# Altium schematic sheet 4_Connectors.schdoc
size 309 x 223 mm; Symbol: Artery_A4; Device: Artery_A4; @Project Name: AT-START-M412; @Page Count: 4; @Create Date: 2024-06-20; Company: Artery Technology; Drawed: SD; Version: 1.0; Page Size: A4; @Update Date: 2024-09-05; @Page No: 4; @Schematic Name: AT-START-M412-V1.0; @Page Name: Connectors; @Board Name: AT-START-M412-V1.0; @Create Time: 16:55:15; @Update Time: 09:29:06
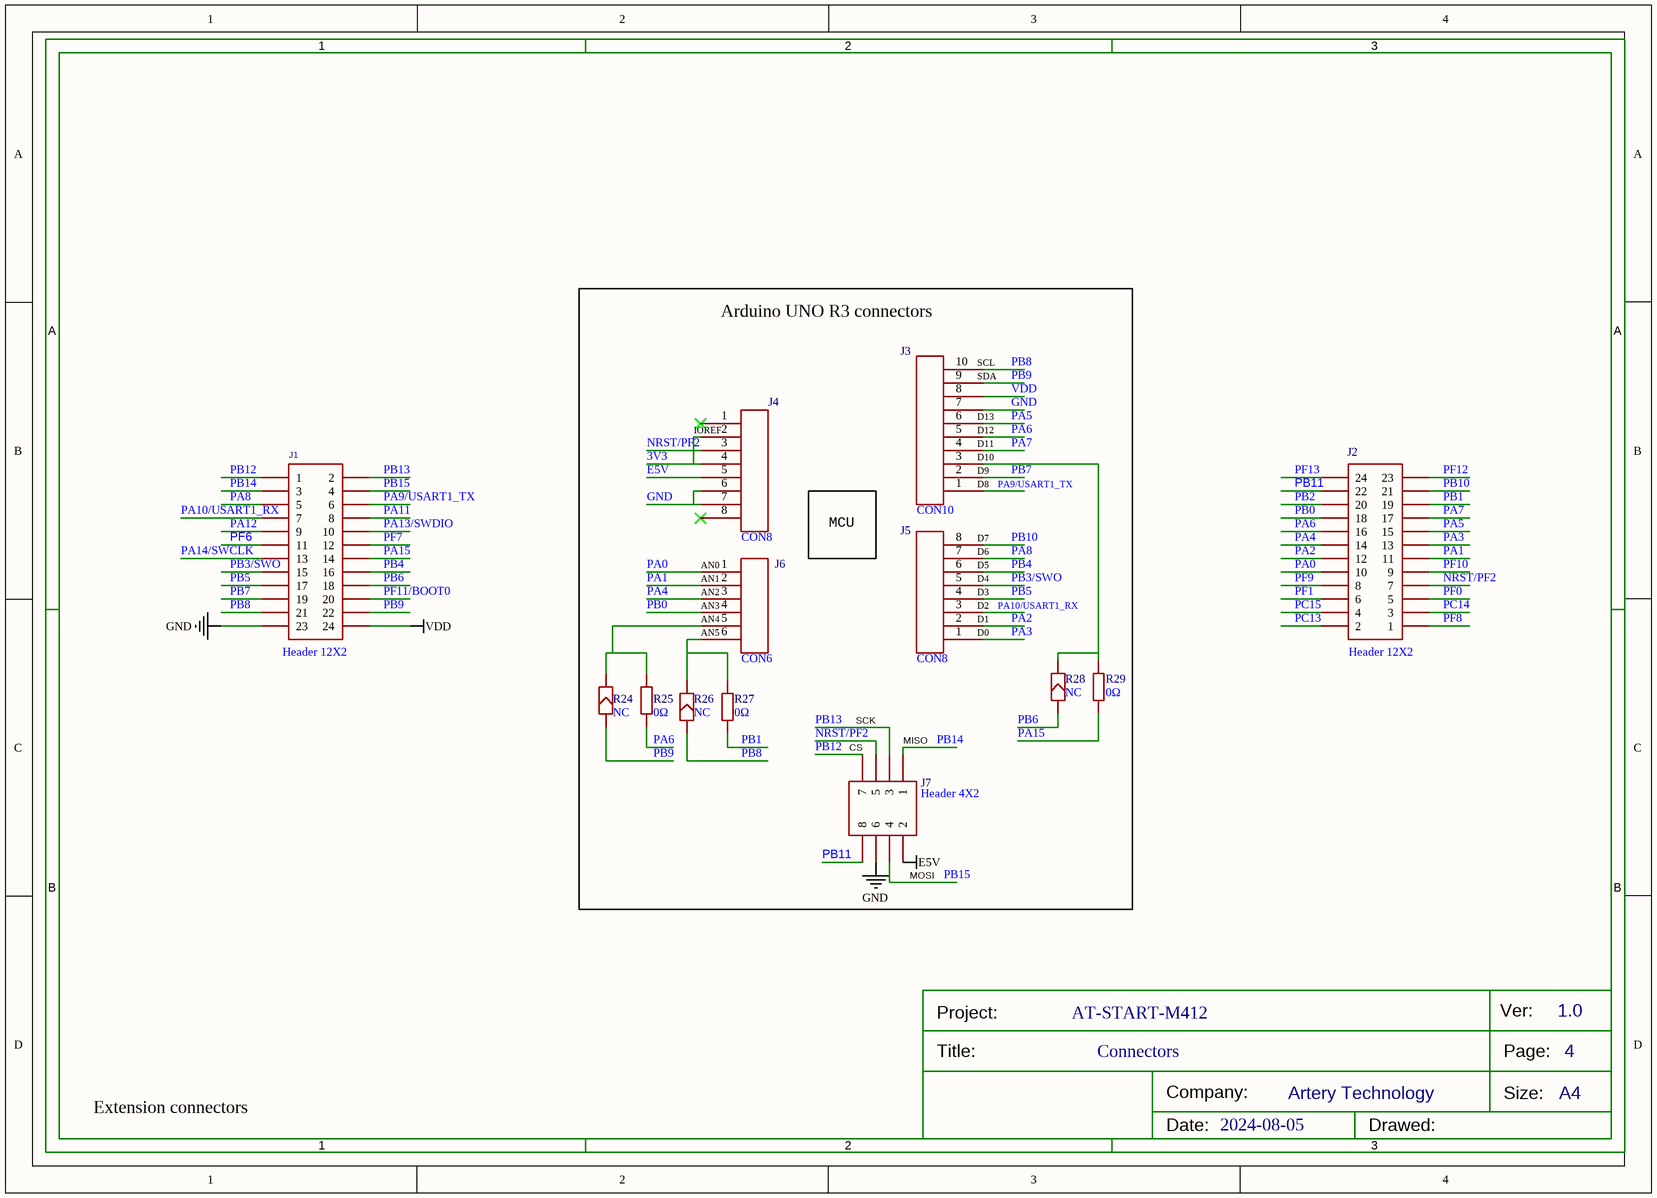
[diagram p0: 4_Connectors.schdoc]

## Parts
J1  Header 12X2  [HEAD2*12]  (value not drawn)
J2  Header 12X2  [HEAD2*12]  (value not drawn)
J3  CON10  [HDR1X10 - 2#]  (value not drawn)
J4  CON8  [HDR1X8 - 2#]  (value not drawn)
J5  CON8  [HDR1X8 - 2#]  (value not drawn)
J6  CON6  [HDR1X6 -2#]  (value not drawn)
J7  Header 4X2  [HDR2X4]  (value not drawn)
R24  NC  [SB-PAD_2]  (value not drawn)
R25  0Ω  [SB-PAD_2]  (value not drawn)
R26  NC  [SB-PAD_2]  (value not drawn)
R27  0Ω  [SB-PAD_2]  (value not drawn)
R28  NC  [SB-PAD_2]  (value not drawn)
R29  0Ω  [SB-PAD_2]  (value not drawn)

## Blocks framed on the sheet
Arduino UNO R3 connectors: J3-J7 R24-R29

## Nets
E5V: J4.5 J7.2
GND: J1.23 J3.7 J4.6 J4.7 J7.6
VDD: J1.24 J3.8
3V3: J4.2 J4.4
NRST/PF2: J2.7 J4.3 J7.5
PA0: J2.10 J6.1
PA1: J2.11 J6.2
PA2: J2.12 J5.2
PA3: J2.13 J5.1
PA4: J2.14 J6.3
PA5: J2.15 J3.6
PA6: J2.16 J3.5 R25.1
PA7: J2.17 J3.4
PA8: J1.5 J5.7
PA9/USART1_TX: J1.6 J3.1
PA10/USART1_RX: J1.7 J5.3
PA11: J1.8
PA12: J1.9
PA13/SWDIO: J1.10
PA14/SWCLK: J1.13
PA15: J1.14 R29.1
PB0: J2.18 J6.4
PB1: J2.19 R27.1
PB2: J2.20
PB3/SWO: J1.15 J5.5
PB4: J1.16 J5.6
PB5: J1.17 J5.4
PB6: J1.18 R28.1
PB7: J1.19 J3.2
PB8: J1.21 J3.10 R26.1
PB9: J1.22 J3.9 R24.1
PB10: J2.21 J5.8
PB11: J2.22 J7.8
PB12: J1.1 J7.7
PB13: J1.2 J7.3
PB14: J1.3 J7.1
PB15: J1.4 J7.4
PC13: J2.2
PC14: J2.3
PC15: J2.4
PF0: J2.5
PF1: J2.6
PF6: J1.11
PF7: J1.12
PF8: J2.1
PF9: J2.8
PF10: J2.9
PF11/BOOT0: J1.20
PF12: J2.23
PF13: J2.24
NetJ3_3: J3.3 R28.2 R29.2
NetJ6_5: J6.5 R24.2 R25.2
NetJ6_6: J6.6 R26.2 R27.2

Not connected (* = marked no-connect by the designer): J4 1* 8*

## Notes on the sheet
- (near J3) SCL
- (near J3) SDA
- (near J4) IOREF
- (near J3) D9
- (near J3) D10
- (near J3) D11
- (near J3) D12
- (near J3) D13
- MCU
- (near J5) D7
- (near J3) D8
- (near J6) AN0
- (near J6) AN1
- (near J6) AN2
- (near J6) AN3
- (near J5) D2
- (near J5) D3
- (near J5) D4
- (near J5) D5
- (near J5) D6
- (near J6) AN4
- (near J6) AN5
- (near J5) D0
- (near J5) D1
- SCK
- (near J7) MISO
- (near J7) CS
- (near J7) MOSI
- AT-START-M412
- Extension connectors
- 2024-08-05

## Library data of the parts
J1 J2 = Header 12X2: 双排直插排针2*12P 2.54mm(黑色); Add into BOM: yes
J3 = CON10: 单排直插排母1*10P 2.54mm(黄色); Symbol: CON10_0; Add into BOM: yes
J4 J5 = CON8: 单排直插排母1*8P 2.54mm(黄色); Add into BOM: yes
J6 = CON6: 单排直插排母1*6P 2.54mm(黄色); Add into BOM: yes
J7 = Header 4X2: 双排直插针2*4P 2.54mm(黄色); Add into BOM: yes
R24 R26 R28 = SB_PAD: 贴片电阻0R,1/10W,5%,0603; Symbol: SB-PAD; Convert to PCB: yes
R25 R27 R29 = 0603WAF0000T5E: 电阻类型:厚膜电阻;阻值:0Ω;精度:±1%;功率:100mW;最大工作电压:75V;; Manufacturer: UNI-ROYAL(厚声); Add into BOM: yes; Tolerance: ±1%; Power(Watts): 100mW; Overload Voltage (Max): 75V; Origin Footprint: SB-PAD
